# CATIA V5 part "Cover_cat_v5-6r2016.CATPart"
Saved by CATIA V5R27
Part number: Cover
Bounding box of the stored display mesh (mm): x -49.99 to 35, y -44.302 to 44.302, z 0 to 30.5
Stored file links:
  E:\_Deepak\2017_Deepak\CATIA\Resources\Tutorial Files\Tutorials\c12_catia_v5_6r2015_tut\c12Tut1\Cover_cat_v5-6r2016.CATPart
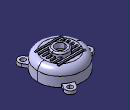
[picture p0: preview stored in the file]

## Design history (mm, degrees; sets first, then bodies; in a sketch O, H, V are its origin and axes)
Body1 (main body)
  Sketch1 on xy-plane, origin (0, 0, 0), H (1, 0, 0), V (0, 1, 0)
    circle A1 centre (0, 0) radius 35
    radius A1 = 35
  Pad1: profile Sketch1, direction (0, 0, 1), length 25
  Fillet1: radius 10, on 1 edge
  Shell1: ExtOffset 0, Face face, IntOffset 2.5
  Sketch2 on face of Pad1, origin (0, 0, 25), H (1, 0, 0), V (0, 1, 0)
    construction line L1 (-20, 0) -> (20, 0)
    point P1 (-20, 0)
    line L2 (-20, 1.75) -> (20, 1.75)
    line L3 (20, -1.75) -> (-20, -1.75)
    arc A1 centre (20, 0) radius 1.75 from (20, 1.75) to (20, -1.75) cw
    arc A2 centre (-20, 0) radius 1.75 from (-20, -1.75) to (-20, 1.75) cw
    length L1 = 40
    radius A1 = 1.75
    distance P1 V = 20
    coincidence: P1 H
    horizontal: L1 H
    tangency: A1 L2, A2 L2, A1 L3, A2 L3
    parallelism: L1 L2
  Pocket1: profile Sketch2, direction (0, 0, -1), length 12.7
  RectPattern1: of Pocket1, direction 1 instances 1, spacing 6, along xy-plane, direction 2 instances 7, spacing 6, along xy-plane, Nv 4
  Sketch3 on face of Shell1, origin (0, 0, 22.5), H (1, 0, 0), V (0, -1, 0)
    circle A1 centre (0, 0) radius 12.5
    radius A1 = 12.5
  Pad2: profile Sketch3, direction (0, 0, 1), length 8
  Fillet2: radius 2, on 1 edge
  Sketch4 on face of Pad2, origin (0, 0, 30.5), H (1, 0, 0), V (0, 1, 0)
    circle A1 centre (0, 0) radius 7.5
    radius A1 = 7.5
  Pocket2: profile Sketch4, direction (0, 0, -1), through (limit type 6)
  Sketch5 on xy-plane, origin (0, 0, 0), H (1, 0, 0), V (0, 1, 0)
    projected arc E1 centre (0, 0) radius 35 from (-34.187, 7.5) to (-34.187, -7.5) ccw from edge of RectPattern1
    line L1 (-34.187, 7.5) -> (-42.5, 7.5)
    line L2 (-34.187, -7.5) -> (-42.5, -7.5)
    arc A1 centre (-42.5, 0) radius 7.5 from (-42.5, -7.5) to (-42.5, 7.5) cw
    point P5 (-42.5, 0)
    point P6 (-50, 0)
    circle A2 centre (-42.5, 0) radius 3.75
    radius A1 = 7.5
    distance V P5 = 42.5
    radius A2 = 3.75
    horizontal: L1 H, L2 H
    coincidence: A1 P6, P6 H, P5 H
    tangency: A1 L2, L1 A1
  Pad3: profile Sketch5, direction (0, 0, 1), length 5
  CircPattern1: of Pad3, instances 3, angular step 120, axis from xy-plane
